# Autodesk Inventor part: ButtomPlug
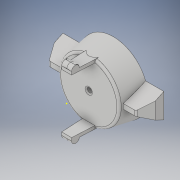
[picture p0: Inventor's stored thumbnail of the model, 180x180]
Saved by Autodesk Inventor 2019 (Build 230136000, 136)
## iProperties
Created: 2021-01
Part Number: ButtomPlug
Material: Generic
Document SubType Name: Modeling
Designer: Johnny Rex Kancaie
Density: 1 g/cm^3
Appearance: Default
Created: 2021-02
Part Number: ButtomPlug_3DPrint
Author: Johnny Rex Kancaie
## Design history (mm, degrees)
sketch "Sketch1"
  geometry: C1 r 28 at (0, 0); 1 further point
  constraints: 1 centre point, 1 coincident
  dimensions: "d0" = 56 diameter of C1
workplane "Work Plane1"
sketch "Sketch2"
  geometry: C1 r 24.5 at (0, 0); 1 further point
  constraints: 1 centre point, 1 coincident
  dimensions: "d2" = 49 diameter of C1
loft "Loft1" sketch "Sketch2" dims "d3" = 0, "d4" = 90 deg, "d5" = 0, "d6" = 90 deg
workplane "Work Plane2"
workplane "Work Plane3"
sketch "Sketch3"
  geometry: L1 (28, 0)-(-28, 0) reference; L2 (-24.5, 20)-(24.5, 20) reference; L3 (-5, 11)-(5, 11); L4 (5, 29)-(-5, 11); L5 (-5, 29)-(5, 11); L6 (-24.5, 20)-(24.5, 20) reference; L7 (5, 20)-(-5, 20); L8 (-4, 38)-(4, 38); L9 (0, 38)-(-4, 38); L10 (-4, 38)-(-5, 20); L11 (0, 38)-(4, 38); L12 (4, 38)-(5, 20); 2 further points
  constraints: 18 end point, 4 midpoint, 1 horizontal, 1 parallel, 1 point on line
  dimensions: "d9" = 10 distance of L3.end L3.start; "d13" = 4 distance of L8.start L9.start
extrude "Extrusion1" join sketch "Sketch3" distance "d15" = 2.5; taper "d16" = 0 deg
sketch "Sketch4"
  geometry: L1 (0, 0.516)-(0, 0) reference; L2 (5, 0)-(0, 0) reference; L3 (10, 0)-(5, 0) reference; L4 (10, 0.516)-(10, 0) reference; L5 (0, 0)-(0, 0.516); L6 (5, 0)-(0, 0) reference; L7 (0, 0)-(5, 0); L8 (0, 2.5)-(0, 0.516) reference; A1 r 24.5 centre (5, 24.5) between (0, 0.516) and (5, 0) reference; A2 r 24.5 centre (5, 24.5) between (5, 0) and (10, 0.516) reference; A3 r 24.5 centre (5, 24.5) between (5, 0) and (10, 0.516) reference; A4 r 24.5 centre (5, 24.5) between (0, 0.516) and (5, 0) reference; A5 r 24.5 centre (5, 24.5) between (0, 0.516) and (5, 0); 1 further point
  constraints: 4 end point, 2 point on circle, 1 centre point, 1 collinear, 1 tangent
extrude "Extrusion2" join sketch "Sketch4" distance "d17" = 4; taper "d18" = 0 deg
sketch "Sketch5"
  geometry: L1 (5, 0)-(0, 0) reference; L2 (5, 0.516)-(5, 0) reference; L3 (5, 0.516)-(5, 0) reference; L4 (5, 0.516)-(5, 0); L5 (5, 0)-(0, 0); A1 r 24.5 centre (0, 24.5) between (0, 0) and (5, 0.516) reference; A2 r 24.5 centre (0, 24.5) between (5, 0.516) and (-5, 0.516) reference; A3 r 24.5 centre (0, 24.5) between (0, 0) and (5, 0.516) reference; A4 r 24.5 centre (0, 24.5) between (0, 0) and (5, 0.516); 1 further point
  constraints: 4 end point, 2 point on circle, 1 centre point, 1 collinear, 1 concentric
extrude "Extrusion3" join sketch "Sketch5" distance "d19" = 4; taper "d20" = 0 deg
sketch "Sketch6"
  geometry: L1 (5, 20)-(5, 11); L2 (5, 11)-(-5, 11); L3 (-5, 11)-(-5, 20); L4 (-5, 29)-(5, 11); L5 (5, 29)-(-5, 11); L6 (4, 38)-(-4, 38); L7 (0, 38)-(-4, 38); L8 (-4, 38)-(-5, 20); L9 (0, 38)-(4, 38); L10 (4, 38)-(5, 20); 3 further points
  constraints: 20 end point, 3 midpoint, 1 parallel, 1 point on line
  dimensions: "d21" = 10 distance of L1.end L2.end; "d24" = 4 distance of L6.end L7.start; "d25" = 4 distance of L6.start L7.start
extrude "Extrusion4" join sketch "Sketch6" distance "d26" = 2.5; taper "d27" = 0 deg
sketch "Sketch7"
  geometry: L1 (-18.028, 0)-(0, 0) reference; L2 (0, 0)-(0, 2.5) reference; L3 (-18.028, 2.5)-(0, 2.5) reference; L4 (-18.028, 1.984)-(-18.028, 2.5) reference; L5 (-18.028, 0)-(-18.028, 1.984) reference; L6 (0, 2.5)-(0.444, 2.5) reference; L7 (-18.028, 2.5)-(0, 2.5) reference; A1 r 3 centre (-3, 2.5) between (0, 2.5) and (-6, 2.5); 1 further point
  constraints: 2 point on circle, 1 centre point, 1 point on line
  dimensions: "d28" = 6 distance of L2.end A1.end; "d29" = 3 radius of A1
  node "Projected Loop5"
sketch "Sketch8"
  geometry: L1 (0, 0)-(18.028, 0) reference; L2 (18.028, 1.984)-(18.028, 0) reference; L3 (18.028, 1.984)-(18.028, 2.5) reference; L4 (0, 2.5)-(18.028, 2.5) reference; L5 (0, 0)-(0, 2.5) reference; L6 (17.473, 2.5)-(-0.444, 2.5) reference; A1 r 3 centre (3, 2.5) between (6, 2.5) and (0, 2.5); 1 further point
  constraints: 2 point on circle, 1 centre point, 1 point on line
  dimensions: "d30" = 6 distance of L4.start A1.start; "d31" = 3 radius of A1
extrude "Extrusion5" join sketch "Sketch8" distance "d32" = 8; taper "d33" = 0 deg
extrude "Extrusion6" join sketch "Sketch7" distance "d34" = 8; taper "d35" = 0 deg
sketch "Sketch9"
  geometry: L1 (-18.028, 2.5)-(0, 2.5) reference; L2 (-18.028, 0.516)-(-18.028, 2.5) reference; L3 (-18.028, 0.516)-(-18.028, 0) reference; L4 (0, 0)-(-18.028, 0) reference; L5 (0, 2.5)-(0, 0) reference; L6 (0, 0)-(-18.028, 0) reference; A1 r 3 centre (-3, 0) between (-6, 0) and (0, 0); 1 further point
  constraints: 2 point on circle, 1 centre point, 1 point on line
  dimensions: "d36" = 6 distance of L4.start A1.start; "d37" = 3 radius of A1
extrude "Extrusion7" join sketch "Sketch9" distance "d38" = 8; taper "d39" = 0 deg
sketch "Sketch10"
  geometry: L1 (0, 2.5)-(18.028, 2.5) reference; L2 (0, 2.5)-(0, 0) reference; L3 (18.028, 0)-(0, 0) reference; L4 (18.028, 0.516)-(18.028, 0) reference; L5 (18.028, 2.5)-(18.028, 0.516) reference; L6 (18.028, 0)-(0, 0) reference; A1 r 3 centre (3, 0) between (0, 0) and (6, 0); 1 further point
  constraints: 2 point on circle, 1 centre point, 1 point on line
  dimensions: "d40" = 6 distance of L2.end A1.end; "d41" = 3 radius of A1
extrude "Extrusion8" join sketch "Sketch10" distance "d42" = 8; taper "d43" = 0 deg
sketch "Sketch11"
  geometry: 1 further point
workplane "Work Plane4"
sketch "Sketch12"
  geometry: L1 (23.984, 20)-(-23.984, 20) reference; L2 (-24.5, 17.114)-(-24.5, 20) reference; L3 (-24.5, 20)-(-24.5, 17.114) reference; L4 (-23.984, 20)-(23.984, 20) reference; L5 (24.5, 17.114)-(24.5, 20) reference; L6 (24.5, 20)-(24.5, 17.114) reference; L7 (28, 0)-(-28, 0) reference; L8 (0, 0)-(0, 17); L9 (0, 0)-(10, 0); L10 (28, 0)-(-28, 0) reference; L11 (0, 17)-(2, 17); L12 (2, 17)-(10, 0); L13 (0, 17)-(-2, 17); L14 (0, 0)-(-10, 0); L15 (-10, 0)-(-2, 17)
  constraints: 14 end point, 3 point on line, 1 parallel, 1 vertical, 4 other
  dimensions: "d47" = 17 distance of L8.start L8.end; "d48" = 10 distance of L8.start L9.end; "d49" = 2 distance of L8.end L11.end; "d50" = 2 distance of L8.end L13.end; "d51" = 10 distance of L8.start L14.end
  node "Projected Loop9"
extrude "Extrusion9" join sketch "Sketch12" distance "d52" = 17; taper "d53" = 0 deg
workplane "Work Plane5"
sketch "Sketch13"
  geometry: L1 (10, 0)-(2, 17) reference; L2 (10, 0)-(2, 17); L3 (2, 17)-(-2, 17) reference; L4 (2, 17)-(-2, 17); L5 (-2, 17)-(-10, 0) reference; L6 (-2, 17)-(-10, 0); L7 (-10, 0)-(10, 0); L8 (28, 0)-(-28, 0) reference; 1 further point
  constraints: 8 end point, 4 collinear
extrude "Extrusion10" join sketch "Sketch13" distance "d55" = 17; taper "d56" = 0 deg
chamfer "Chamfer1" distance "d57" = 10; stored, may be unused: second distance "d58" = 2, angle "d59" = 30 deg
chamfer "Chamfer2" distance "d60" = 10; stored, may be unused: second distance "d61" = 2, angle "d62" = 30 deg
fillet "Fillet3" dims "d63" = 2
sketch "Sketch14"
  geometry: C1 r 21.5 at (41, -10); 1 further point
  constraints: 1 centre point, 1 coincident
  dimensions: "d64" = 43 diameter of C1
extrude "Extrusion11" cut sketch "Sketch14" distance "d65" = 16; taper "d66" = 0 deg
sketch "Sketch15"
  geometry: L1 (14.847, 0)-(0, 0) reference; L2 (0, -20)-(0, 0) reference; L3 (14.847, -20)-(0, -20) reference; L4 (67.153, -20)-(82, -20) reference; L5 (82, 0)-(82, -20) reference; L6 (67.153, 0)-(82, 0) reference; L7 (14.847, 0)-(0, 0) reference; L8 (0, -20)-(0, 0) reference; L9 (14.847, -20)-(0, -20) reference; L10 (2.969, -16)-(10.969, -16); L11 (10.969, -16)-(10.969, -4); L12 (10.969, -4)-(2.969, -4); L13 (2.969, -4)-(2.969, -16); L14 (2.969, -16)-(10.969, -4); L15 (10.969, -16)-(2.969, -4); L16 (67.153, 0)-(82, 0) reference; L17 (82, 0)-(82, -20) reference; L18 (71.072, -16)-(79.072, -16); L19 (79.072, -16)-(79.072, -4); L20 (79.072, -4)-(71.072, -4); L21 (71.072, -4)-(71.072, -16); L22 (75.072, -12)-(75.072, -8) reference; L23 (71.072, -16)-(79.072, -4); L24 (79.072, -16)-(71.072, -4); C1 r 21.5 at (41, -10) reference; A1 r 28 centre (41, -10) between (67.153, 0) and (14.847, 0) reference; A2 r 28 centre (41, -10) between (14.847, -20) and (67.153, -20) reference; 3 further points
  constraints: 24 end point, 5 midpoint, 4 parallel, 2 horizontal, 2 perpendicular
  dimensions: "d67" = 12 distance of L12.end L10.start; "d68" = 12 distance of L18.end L19.end; "d69" = 8 distance of L19.end L20.end; "d70" = 8 distance of L11.end L12.end
extrude "Extrusion12" cut sketch "Sketch15" distance "d71" = 6; taper "d72" = 0 deg
sketch "Sketch18"
  geometry: C1 r 21.5 at (0, 0) reference; C2 r 2 at (0, 0); 1 further point
  constraints: 1 centre point, 1 coincident
  dimensions: "d77" = 4 diameter of C2
extrude "Extrusion15" cut sketch "Sketch18" extent not by distance; stored distance "d78" = 2; taper "d79" = 0 deg
fillet "Fillet5" dims "d81" = 2
sketch "Sketch20"
  geometry: C1 r 25 at (41, -10); 1 further point
  constraints: 1 centre point, 1 coincident
  dimensions: "d82" = 50 diameter of C1
extrude "Extrusion16" cut sketch "Sketch20" distance "d83" = 8; taper "d84" = 0 deg
fillet "Fillet6" dims "d85" = 5
fillet "Fillet7" dims "d86" = 2
fillet "Fillet8" dims "d87" = 1
body "Solid1"
node "Projected Loop1"
node "Projected Loop2"
node "Projected Loop3"
node "Projected Loop4"
node "Projected Loop6"
node "Projected Loop7"
node "Projected Loop8"
node "Projected Loop10"
node "Projected Loop13"
other parameters: "d7" = 22, "d8" = -22, "d46" = 24, "d54" = -24
